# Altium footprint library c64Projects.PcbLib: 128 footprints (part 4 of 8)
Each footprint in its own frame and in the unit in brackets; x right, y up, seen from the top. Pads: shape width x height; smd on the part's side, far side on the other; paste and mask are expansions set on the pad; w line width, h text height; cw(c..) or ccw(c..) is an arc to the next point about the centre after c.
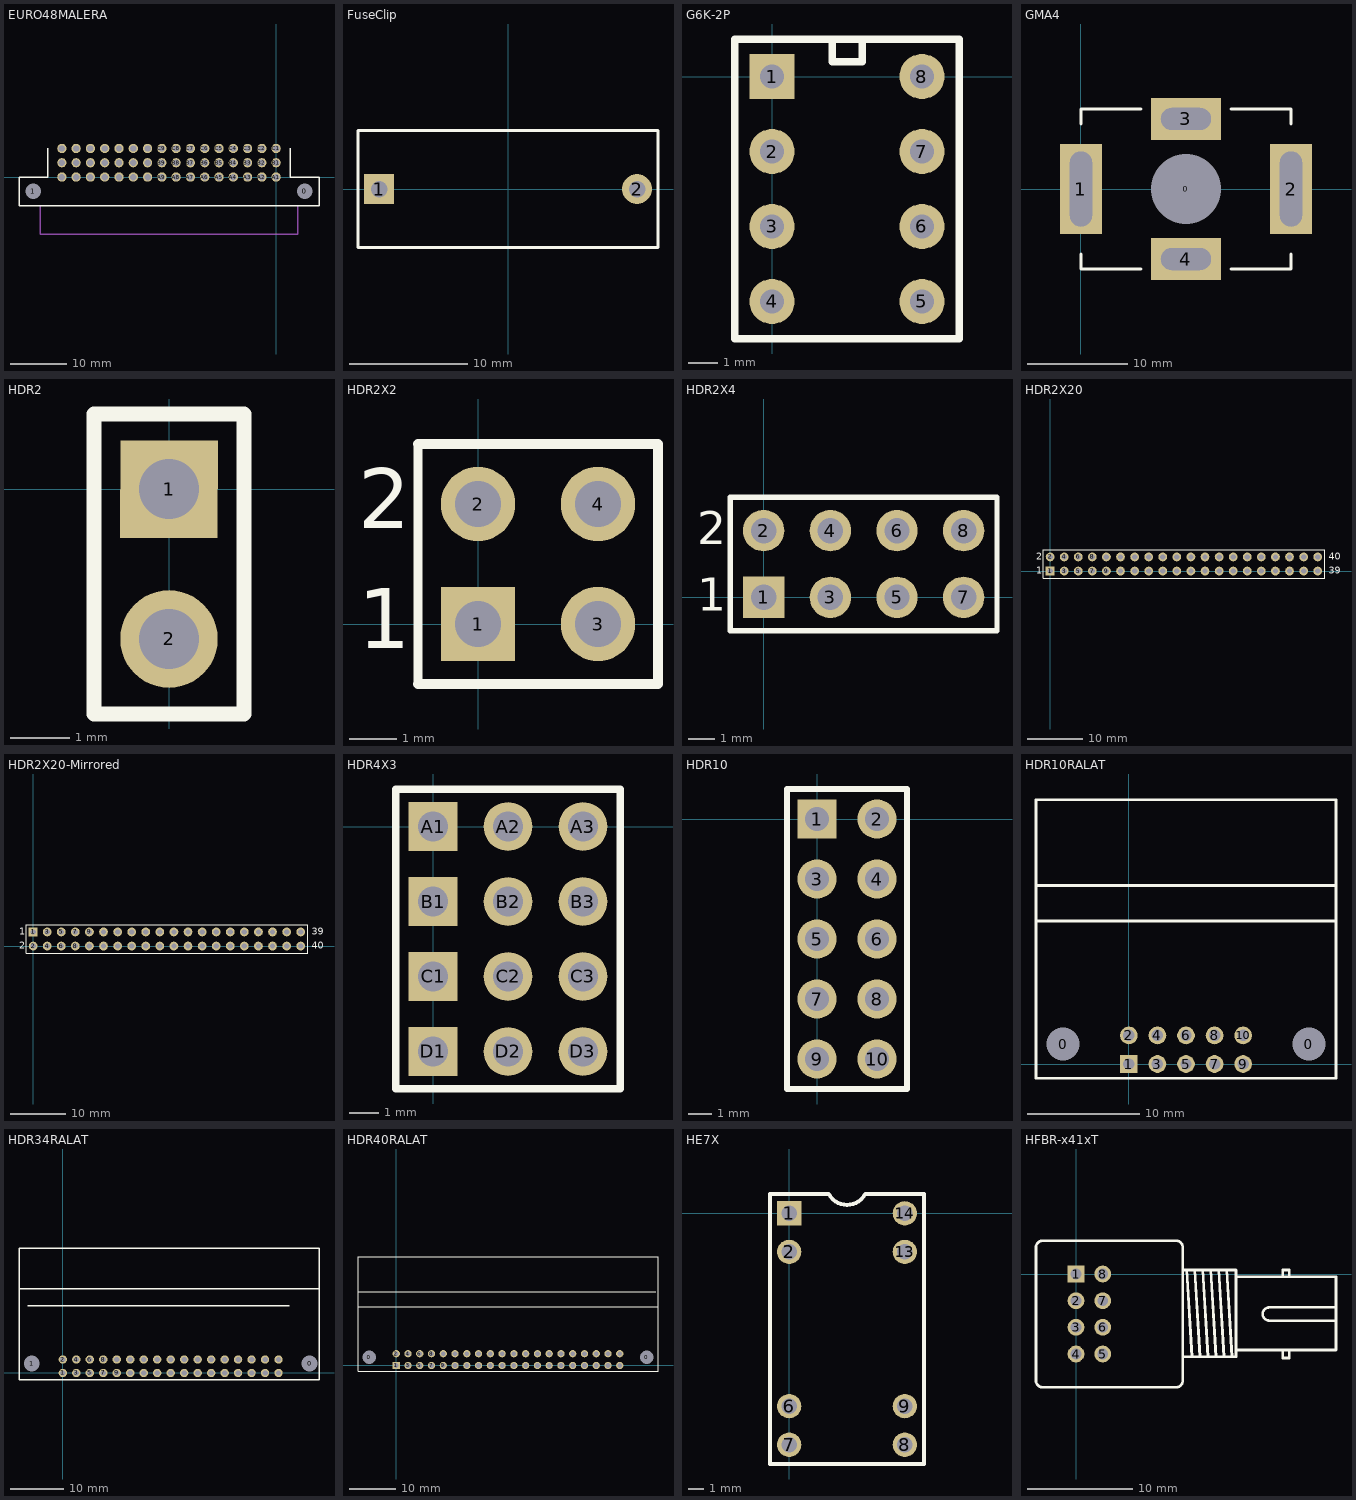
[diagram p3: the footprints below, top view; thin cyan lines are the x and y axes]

## EURO48MALERA [mil]
pads (50):
  round 65 hole 110 unplated: 0(200,-100) 1(-1700,-100)
  round 65 hole 45: A1(0,0) A2(-100,0) A3(-200,0) A4(-300,0) A5(-400,0) A6(-500,0) A7(-600,0) A8(-700,0) A9(-800,0) A10(-900,0) A11(-1000,0) A12(-1100,0) A13(-1200,0) A14(-1300,0) A15(-1400,0) A16(-1500,0) B1(0,100) B2(-100,100) B3(-200,100) B4(-300,100) B5(-400,100) B6(-500,100) B7(-600,100) B8(-700,100) B9(-800,100) B10(-900,100) B11(-1000,100) B12(-1100,100) B13(-1200,100) B14(-1300,100) B15(-1400,100) B16(-1500,100) C1(0,200) C2(-100,200) C3(-200,200) C4(-300,200) C5(-400,200) C6(-500,200) C7(-600,200) C8(-700,200) C9(-800,200) C10(-900,200) C11(-1000,200) C12(-1100,200) C13(-1200,200) C14(-1300,200) C15(-1400,200) C16(-1500,200)
Top Overlay:
  lines w10: -1600,200 -1600,0 -1800,0 -1800,-200 300,-200 300,0 100,0 100,200
3D Top:
  lines w10: -1650,-200 -1650,-400 150,-400 150,-200

## FuseClip [mil]
pads (2):
  rect 100x100 hole 55: 1(-430,0)
  round 100 hole 55: 2(430,0)
Top Overlay:
  lines w10: -500,-195 500,-195 500,195 -500,195 -500,-195

## G6K-2P [mil]
pads (8):
  rect 60x60 hole 32: 1(0,0)
  round 60 hole 32: 2(0,-100) 3(0,-200) 4(0,-300) 5(200,-300) 6(200,-200) 7(200,-100) 8(200,0)
Top Overlay:
  lines w10: 80,50 80,20 120,20 120,50 ; -50,-350 250,-350 250,50 -50,50 -50,-350

## GMA4 [mm]
pads (5):
  round 1 hole 7 unplated: 0(10.5,0)
  rect 4.2x9 hole 2.2 slot 7.5 at 90 deg: 1(0,0) 2(21,0)
  rect 7x4.2 hole 2.2 slot 5 at 0 deg: 3(10.5,7) 4(10.5,-7)
Top Overlay:
  lines w0.254: 0,-6.5 0,-8 6,-8 ; 0,6.5 0,8 6,8 ; 15,-8 21,-8 21,-6.5 ; 15,8 21,8 21,6.5
3D body: height 15, standoff 0, extent 0,-8 21,8

## HDR2 [mil]
pads (2):
  rect 65x65 hole 40: 1(0,0)
  round 65 hole 40: 2(0,-100)
Top Overlay:
  lines w10: -50,-150 -50,50 50,50 50,-150 -50,-150

## HDR2X2 [mil]
pads (4):
  rect 62x62 hole 38: 1(0,0)
  round 62 hole 38: 2(0,100) 3(100,0) 4(100,100)
Top Overlay:
  lines w7.87: -50,-50 -50,150
  lines w8: -50,-50 150,-50 150,150 -50,150
  text "2" at -100,80 h50
  text "1" at -100,-20 h50

## HDR2X4 [mil]
pads (8):
  rect 62x62 hole 38: 1(0,0)
  round 62 hole 38: 2(0,100) 3(100,0) 4(100,100) 5(200,0) 6(200,100) 7(300,0) 8(300,100)
Top Overlay:
  lines w7.87: -50,-50 -50,150
  lines w8: -50,-50 350,-50 350,150 -50,150
  text "1" at -100,-20 h50
  text "2" at -100,80 h50

## HDR2X20 [mil] "Connector; Header; 20x2 Position"
pads (40):
  rect 62x62 hole 38: 1(0,0)
  round 62 hole 38: 2(0,100) 3(100,0) 4(100,100) 5(200,0) 6(200,100) 7(300,0) 8(300,100) 9(400,0) 10(400,100) 11(500,0) 12(500,100) 13(600,0) 14(600,100) 15(700,0) 16(700,100) 17(800,0) 18(800,100) 19(900,0) 20(900,100) 21(1000,0) 22(1000,100) 23(1100,0) 24(1100,100) 25(1200,0) 26(1200,100) 27(1300,0) 28(1300,100) 29(1400,0) 30(1400,100) 31(1500,0) 32(1500,100) 33(1600,0) 34(1600,100) 35(1700,0) 36(1700,100) 37(1800,0) 38(1800,100) 39(1900,0) 40(1900,100)
Top Overlay:
  lines w7.87: -50,-50 1950,-50 1950,150 -50,150 -50,-50
  text "1" at -100,-20 h50
  text "2" at -100,80 h50
  text "40" at 1980,80 h50
  text "39" at 1980,-20 h50

## HDR2X20-Mirrored [mil] "Connector; Header; 20x2 Position"
pads (40):
  rect 62x62 hole 38: 1(0,100)
  round 62 hole 38: 2(0,0) 3(100,100) 4(100,0) 5(200,100) 6(200,0) 7(300,100) 8(300,0) 9(400,100) 10(400,0) 11(500,100) 12(500,0) 13(600,100) 14(600,0) 15(700,100) 16(700,0) 17(800,100) 18(800,0) 19(900,100) 20(900,0) 21(1000,100) 22(1000,0) 23(1100,100) 24(1100,0) 25(1200,100) 26(1200,0) 27(1300,100) 28(1300,0) 29(1400,100) 30(1400,0) 31(1500,100) 32(1500,0) 33(1600,100) 34(1600,0) 35(1700,100) 36(1700,0) 37(1800,100) 38(1800,0) 39(1900,100) 40(1900,0)
Top Overlay:
  lines w7.87: -50,-50 1950,-50 1950,150 -50,150 -50,-50
  text "1" at -100,80 h50
  text "2" at -100,-20 h50
  text "40" at 1980,-20 h50
  text "39" at 1980,80 h50

## HDR4X3 [mil]
pads (12):
  rect 65x65 hole 40: A1(0,0) B1(0,-100) C1(0,-200) D1(0,-300)
  round 65 hole 40: A2(100,0) A3(200,0) B2(100,-100) B3(200,-100) C2(100,-200) C3(200,-200) D2(100,-300) D3(200,-300)
Top Overlay:
  lines w10: -50,-350 250,-350 250,50 -50,50 -50,-350

## HDR10 [mil]
pads (10):
  rect 65x65 hole 40: 1(0,0)
  round 65 hole 40: 2(100,0) 3(0,-100) 4(100,-100) 5(0,-200) 6(100,-200) 7(0,-300) 8(100,-300) 9(0,-400) 10(100,-400)
Top Overlay:
  lines w10: -50,-450 150,-450 150,50 -50,50 -50,-450

## HDR10RALAT [mil]
pads (12):
  round 62 hole 116 unplated: 0(-230,70) 0(630,70)
  rect 62x62 hole 40: 1(0,0)
  round 62 hole 40: 2(0,100) 3(100,0) 4(100,100) 5(200,0) 6(200,100) 7(300,0) 8(300,100) 9(400,0) 10(400,100)
Top Overlay:
  lines w10: -325,500 725,500 ; 725,625 -325,625 ; -325,625 -325,925 725,925 725,-50 -325,-50 -325,625

## HDR34RALAT [mil]
pads (36):
  round 62 hole 116: 0(1830,70) 1(-230,70)
  round 62 hole 40: 1(0,0) 2(0,100) 3(100,0) 4(100,100) 5(200,0) 6(200,100) 7(300,0) 8(300,100) 9(400,0) 10(400,100) 11(500,0) 12(500,100) 13(600,0) 14(600,100) 15(700,0) 16(700,100) 17(800,0) 18(800,100) 19(900,0) 20(900,100) 21(1000,0) 22(1000,100) 23(1100,0) 24(1100,100) 25(1200,0) 26(1200,100) 27(1300,0) 28(1300,100) 29(1400,0) 30(1400,100) 31(1500,0) 32(1500,100) 33(1600,0) 34(1600,100)
Top Overlay:
  lines w10: -260,500 1680,500 ; -325,625 -325,-50 1900,-50 1900,625 ; -325,625 1900,625 ; -325,625 -325,925 1900,925 1900,625

## HDR40RALAT [mil]
pads (42):
  round 62 hole 116 unplated: 0(-230,70) 0(2130,70)
  rect 62x62 hole 40: 1(0,0)
  round 62 hole 40: 2(0,100) 3(100,0) 4(100,100) 5(200,0) 6(200,100) 7(300,0) 8(300,100) 9(400,0) 10(400,100) 11(500,0) 12(500,100) 13(600,0) 14(600,100) 15(700,0) 16(700,100) 17(800,0) 18(800,100) 19(900,0) 20(900,100) 21(1000,0) 22(1000,100) 23(1100,0) 24(1100,100) 25(1200,0) 26(1200,100) 27(1300,0) 28(1300,100) 29(1400,0) 30(1400,100) 31(1500,0) 32(1500,100) 33(1600,0) 34(1600,100) 35(1700,0) 36(1700,100) 37(1800,0) 38(1800,100) 39(1900,0) 40(1900,100)
Top Overlay:
  lines w10: -325,500 2225,500 ; 2205,625 -325,625 ; -325,625 -325,925 2225,925 2225,-50 -325,-50 -325,625

## HE7X [mil]
pads (8):
  rect 63x63 hole 40: 1(0,0)
  round 63 hole 40: 2(0,-100) 6(0,-500) 7(0,-600) 8(300,-600) 9(300,-500) 13(300,-100) 14(300,0)
Top Overlay:
  lines w10: 102.56,50 -50,50 -50,-650 350,-650 350,50 197.44,50 ; 104.07,48.48 ccw(c150,75) 195.93,48.48

## HFBR-x41xT [mil]
pads (8):
  rect 63x63 hole 40: 1(0,0)
  round 63 hole 40: 2(0,-100) 3(0,-200) 4(0,-300) 5(100,-300) 6(100,-200) 7(100,-100) 8(100,0)
Top Overlay:
  lines w10: 400,-310 600,-310 600,15 400,15 ; 415,15 435,-310 ; 445,15 465,-310 ; 475,15 495,-310 ; 505,15 525,-310 ; 535,15 555,-310 ; 565,15 585,-310 ; 600,-285 975,-285 975,-10 600,-10 ; 775,-290 775,-315 800,-315 800,-290 ; 775,-10 775,15 800,15 800,-10 ; 975,-175 725,-175 cw(c725,-150) 725,-125 975,-125 ; -150,-400 ccw(c-125,-400) -125,-425 375,-425 ccw(c375,-400) 400,-400 400,100 ccw(c375,100) 375,125 -125,125 ccw(c-125,100) -150,100 -150,-400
